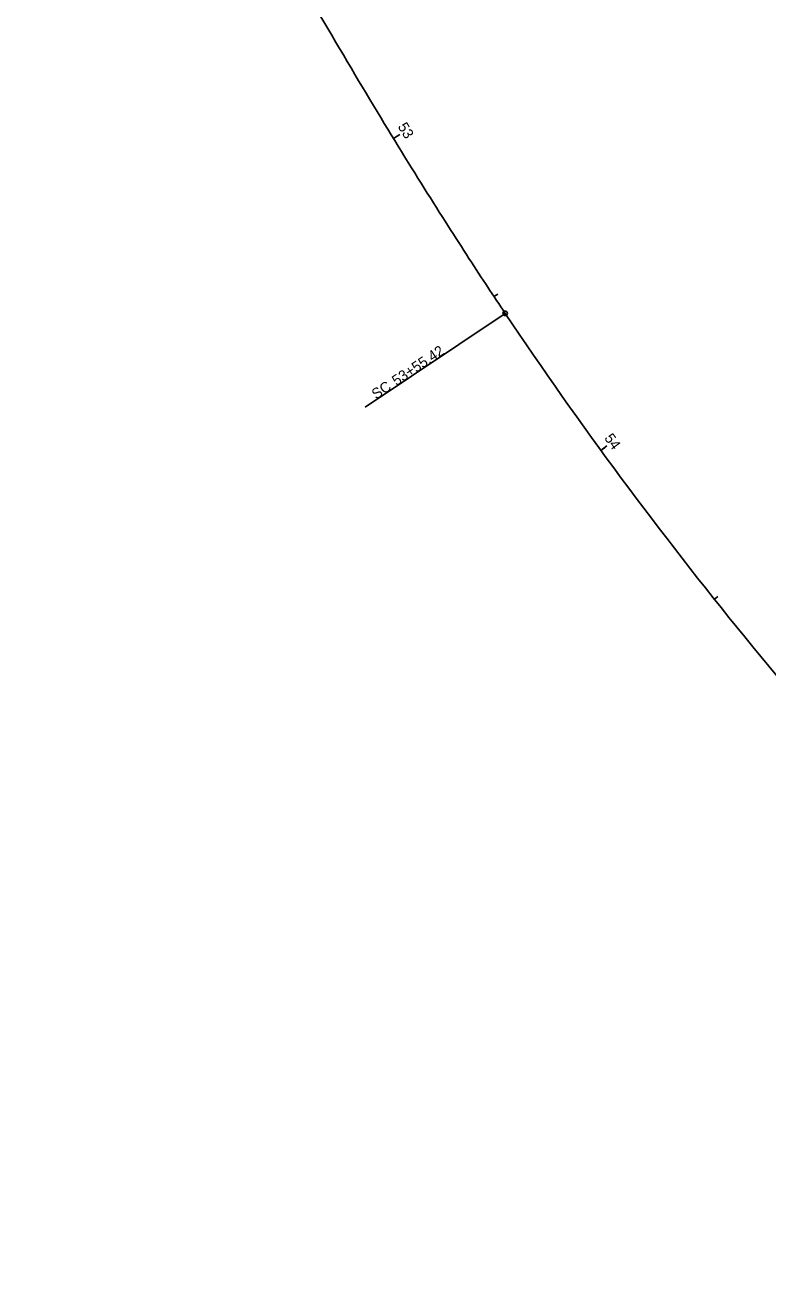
# Model space of a CAD drawing. Extents: x 1492452 to 1496782, y 514026 to 517659.
# Drawn here: x 1494344.2 to 1494542.5, y 514788.1 to 515125.3 of the extents above; entities that cross this region are included whole.
import ezdxf

# ---------------------------------------------------------------- set-up
doc = ezdxf.new("R2010")
doc.units = 0
for name, color, linetype in [('Default', 7, 'Continuous'), ('GE_X_Cells', 7, 'Continuous'), ('PV_X_EOP', 7, 'Continuous'), ('PV_X_Shoulder_Aggregate', 7, 'Continuous'), ('RD_X_GR_Rt', 7, 'Continuous'), ('RD_X_Wall', 7, 'Continuous'), ('SV_X_Top_of_Bank', 7, 'Continuous'), ('XS_X_Ground_Line', 7, 'Continuous')]:
    doc.layers.add(name, color=color, linetype=linetype)

msp = doc.modelspace()

# ---------------------------------------------------------------- linework, layer by layer
at = {"layer": 'Default'}
msp.add_arc((1486425.91, 524780.42), 12277.67, 302.444021, 313.600151, dxfattribs=at)
at = {"layer": 'GE_X_Cells'}
msp.add_arc((1486425.91, 524780.42), 12277.67, 302.444021, 313.600151, dxfattribs=at)
at = {"layer": 'PV_X_EOP'}
msp.add_line((1494472.4, 515048.36), (1494435.02, 515023.3), dxfattribs=at)
msp.add_circle((1494472.4, 515048.36), 0.6, dxfattribs=at)
at = {"layer": 'PV_X_Shoulder_Aggregate'}
for p, q in [((1494442.57, 515095.05), (1494444.28, 515096.09)), ((1494469.4, 515052.86), (1494470.4, 515053.52)), ((1494497.94, 515011.81), (1494499.56, 515012.99)), ((1494528.24, 514972.05), (1494529.18, 514972.8))]:
    msp.add_line(p, q, dxfattribs=at)
at = {"layer": 'RD_X_GR_Rt'}
msp.add_line((1494472.4, 515048.36), (1494435.02, 515023.3), dxfattribs=at)
msp.add_circle((1494472.4, 515048.36), 0.6, dxfattribs=at)
at = {"layer": 'RD_X_Wall'}
for p, q in [((1494442.57, 515095.05), (1494443.59, 515095.68)), ((1494497.94, 515011.81), (1494498.91, 515012.52))]:
    msp.add_line(p, q, dxfattribs=at)
at = {"layer": 'SV_X_Top_of_Bank'}
msp.add_arc((1495424.3, 515686.35), 1145.92, 213.83122, 224.58118, dxfattribs=at)
msp.add_arc((1495424.3, 515686.35), 1145.92, 213.83122, 224.58118, dxfattribs=at)
msp.add_open_spline([(1494370.94, 515220.63), (1494373.62, 515215.76), (1494378.97, 515206.03), (1494389.71, 515186.57), (1494403.23, 515162.3), (1494419.72, 515133.34), (1494436.64, 515104.61), (1494451.2, 515080.96), (1494463.19, 515062.25), (1494469.31, 515052.97), (1494472.4, 515048.36)], degree=3, dxfattribs=at)
msp.add_open_spline([(1494370.94, 515220.63), (1494373.62, 515215.76), (1494378.97, 515206.03), (1494389.71, 515186.57), (1494403.23, 515162.3), (1494419.72, 515133.34), (1494436.64, 515104.61), (1494451.2, 515080.96), (1494463.19, 515062.25), (1494469.31, 515052.97), (1494472.4, 515048.36)], degree=3, dxfattribs=at)
at = {"layer": 'XS_X_Ground_Line'}
msp.add_line((1494472.4, 515048.36), (1494435.02, 515023.3), dxfattribs=at)
msp.add_circle((1494472.4, 515048.36), 0.6, dxfattribs=at)

# ---------------------------------------------------------------- texts
at = {"layer": 'PV_X_EOP'}
for s, p in [('53+55.42', (1494443.34, 515028.93)), ('SC', (1494437.92, 515025.3))]:
    msp.add_text(s, height=2.8, rotation=33.8312, dxfattribs=at).set_placement(p)
at = {"layer": 'PV_X_Shoulder_Aggregate'}
for s, rotation, p in [('53', 301.4443, (1494443.61, 515098.24)), ('54', 306.0605, (1494498.73, 515015.05))]:
    msp.add_text(s, height=2.8, rotation=rotation, dxfattribs=at).set_placement(p)
at = {"layer": 'RD_X_GR_Rt'}
for s, p in [('53+55.42', (1494443.34, 515028.93)), ('SC', (1494437.92, 515025.3))]:
    msp.add_text(s, height=2.8, rotation=33.8312, dxfattribs=at).set_placement(p)
at = {"layer": 'XS_X_Ground_Line'}
for s, p in [('53+55.42', (1494443.34, 515028.93)), ('SC', (1494437.92, 515025.3))]:
    msp.add_text(s, height=2.8, rotation=33.8312, dxfattribs=at).set_placement(p)

doc.saveas('drawing.dxf')
